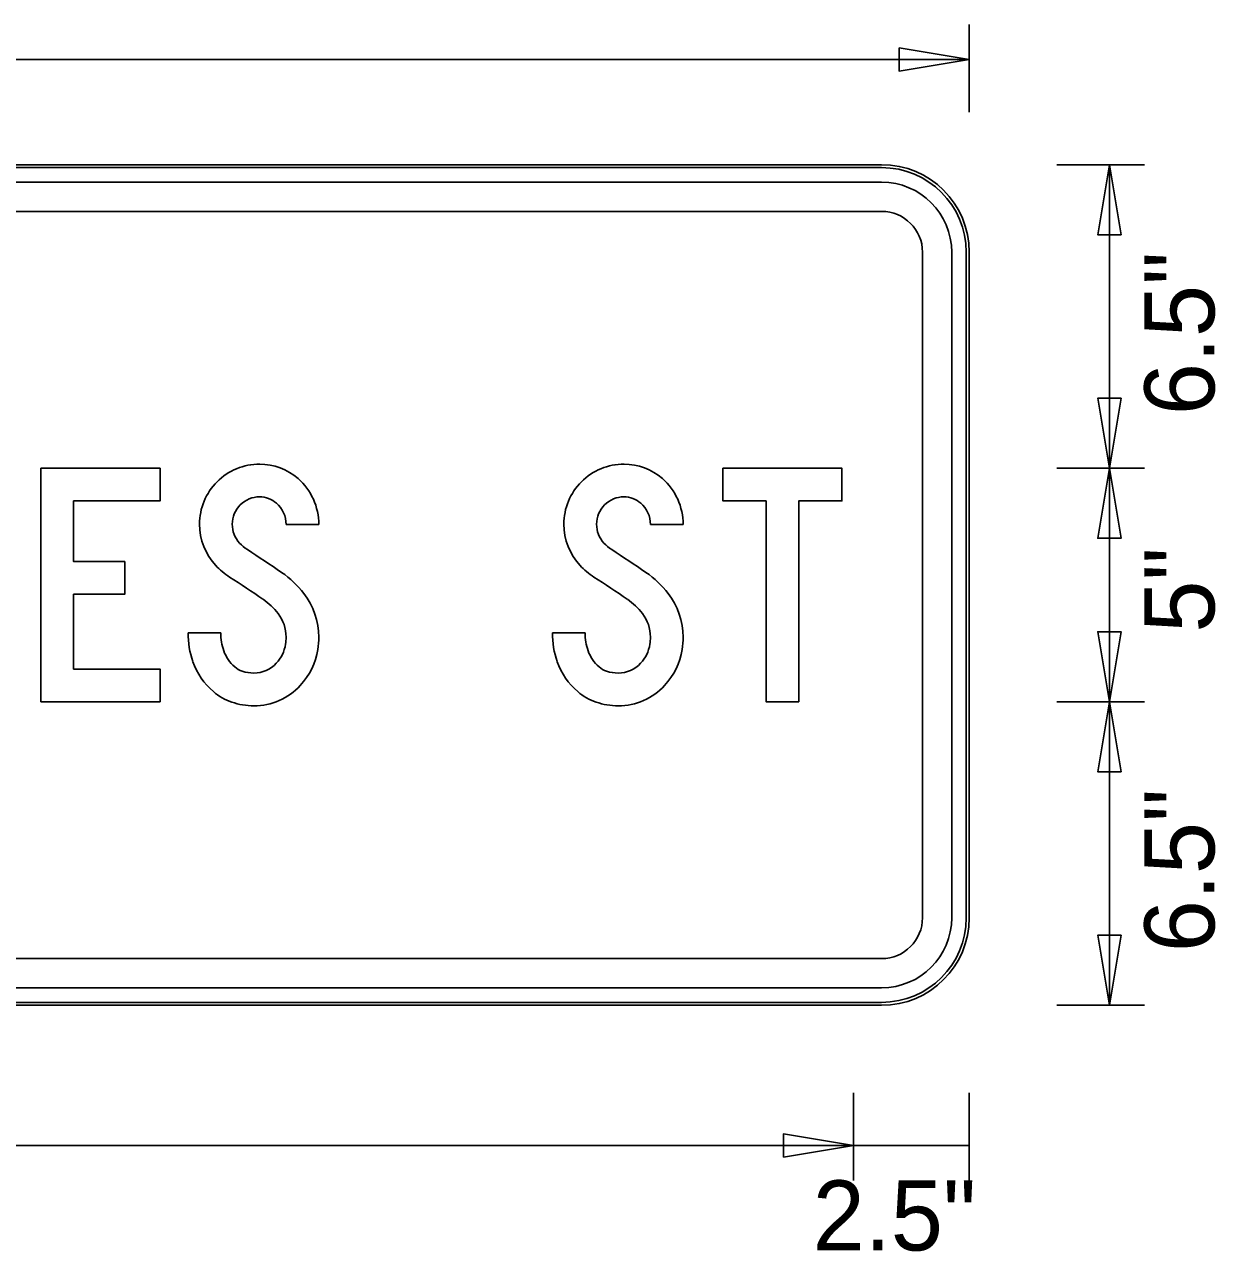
# Model space of a CAD drawing. Extents: x 1788.1 to 1851.2, y 237.2 to 283.4.
# Drawn here: x 1841.615 to 1844.165, y 250.141 to 252.768 of the extents above; entities that cross this region are included whole.
import ezdxf

# ---------------------------------------------------------------- set-up
doc = ezdxf.new("R2010")
doc.units = 0
for name, color, linetype in [('GSBWFILL', 7, 'Continuous'), ('GSCOLORFILL', 7, 'Continuous'), ('GSDIMS', 7, 'Continuous'), ('GSOUTLINE', 7, 'Continuous')]:
    doc.layers.add(name, color=color, linetype=linetype)

msp = doc.modelspace()

# ---------------------------------------------------------------- linework, layer by layer
at = {"layer": 'GSBWFILL'}
for p, q in [((1843.4504, 252.4677), (1839.0254, 252.4677)), ((1843.4504, 252.4302), (1839.0254, 252.4302)), ((1839.0254, 252.3677), (1843.4504, 252.3677)), ((1843.5379, 252.2802), (1843.5379, 250.8552)), ((1843.6004, 250.8552), (1843.6004, 252.2802)), ((1843.6379, 250.8552), (1843.6379, 252.2802)), ((1843.4504, 250.7677), (1839.026, 250.7677)), ((1839.026, 250.7052), (1843.4504, 250.7052)), ((1839.0254, 250.6677), (1843.4504, 250.6677))]:
    msp.add_line(p, q, dxfattribs=at)
for points in [[(1841.7204, 251.3877), (1841.7204, 251.5477), (1841.8299, 251.5477), (1841.8299, 251.6177), (1841.7204, 251.6177), (1841.7204, 251.7477), (1841.9054, 251.7477), (1841.9054, 251.8177), (1841.6504, 251.8177), (1841.6504, 251.3177), (1841.9054, 251.3177), (1841.9054, 251.3877)], [(1843.2029, 251.7477), (1843.1104, 251.7477), (1843.1104, 251.8177), (1843.3654, 251.8177), (1843.3654, 251.7477), (1843.2729, 251.7477), (1843.2729, 251.3177), (1843.2029, 251.3177)]]:
    msp.add_lwpolyline(points, close=True, dxfattribs=at)
for points in [[(1842.1754, 251.6973), (1842.2454, 251.6973)], [(1842.9554, 251.6973), (1843.0254, 251.6973)], [(1842.0354, 251.4649), (1841.9654, 251.4649)], [(1842.8154, 251.4649), (1842.7454, 251.4649)]]:
    msp.add_lwpolyline(points, dxfattribs=at)
for centre, radius, start, end in [((1843.4504, 252.2802), 0.1875, 0, 90), ((1843.4504, 252.2802), 0.15, 0, 90), ((1843.4504, 252.2802), 0.0875, 0, 90), ((1843.4504, 250.8552), 0.15, 270, 0), ((1843.4504, 250.8552), 0.0875, 270, 0), ((1843.4504, 250.8552), 0.1875, 270, 0)]:
    msp.add_arc(centre, radius, start, end, dxfattribs=at)
for centre, major_axis, start_param, end_param in [((1842.1188, 251.6977), (0, 0.1288), 6.283184, 7.853982), ((1842.1188, 251.7021), (0, 0.1244), 5.561989, 6.283185), ((1842.8988, 251.6977), (0, 0.1288), 6.283184, 7.853982), ((1842.8988, 251.7021), (0, 0.1244), 5.561989, 6.283185), ((1842.1147, 251.6973), (0, 0.1307), 4.712389, 5.561989), ((1842.8947, 251.6973), (0, 0.1307), 4.712389, 5.561989), ((1842.1188, 251.6977), (0, 0.0588), 6.283183, 7.853981), ((1842.1188, 251.7021), (0, 0.0544), 5.561989, 6.283185), ((1842.1147, 251.6973), (0, 0.0607), 4.712389, 5.561989), ((1842.8988, 251.6977), (0, 0.0588), 6.283183, 7.853981), ((1842.8988, 251.7021), (0, 0.0544), 5.561989, 6.283185), ((1842.8947, 251.6973), (0, 0.0607), 4.712389, 5.561989), ((1842.1191, 251.6977), (0, 0.1291), 1.570796, 2.321595), ((1842.1191, 251.6977), (0, 0.0591), 1.570796, 2.321595), ((1842.8991, 251.6977), (0, 0.1291), 1.570796, 2.321595), ((1842.8991, 251.6977), (0, 0.0591), 1.570796, 2.321595), ((1842.1403, 251.7175), (0, 0.0881), 2.321595, 2.56746), ((1842.9203, 251.7175), (0, 0.0881), 2.321595, 2.56746), ((1840.4942, 249.1726), (0, 2.9428), 5.679143, 5.709053), ((1841.2742, 249.1726), (0, 2.9428), 5.679143, 5.709053), ((1842.1403, 251.7175), (0, 0.1581), 2.321595, 2.56746), ((1842.9203, 251.7175), (0, 0.1581), 2.321595, 2.56746), ((1840.4942, 249.1726), (0, 2.8728), 5.679143, 5.709053), ((1842.0434, 251.4174), (0, 0.2153), 5.373599, 5.679143), ((1841.2742, 249.1726), (0, 2.8728), 5.679143, 5.709053), ((1842.8234, 251.4174), (0, 0.2153), 5.373599, 5.679143), ((1842.0931, 251.4561), (0, 0.1523), 4.712389, 5.373599), ((1842.8731, 251.4561), (0, 0.1523), 4.712389, 5.373599), ((1842.0434, 251.4174), (0, 0.1453), 5.373599, 5.679143), ((1842.8234, 251.4174), (0, 0.1453), 5.373599, 5.679143), ((1842.0931, 251.4561), (0, 0.0823), 4.712389, 5.373599), ((1842.8731, 251.4561), (0, 0.0823), 4.712389, 5.373599), ((1842.1498, 251.4649), (0, 0.1844), 1.570808, 1.909921), ((1842.1498, 251.4649), (0, 0.1144), 1.570816, 1.909918), ((1842.0789, 251.4561), (0, 0.0965), 4.552917, 4.712389), ((1842.0789, 251.4561), (0, 0.1665), 4.552917, 4.712389), ((1842.9298, 251.4649), (0, 0.1844), 1.570808, 1.909921), ((1842.9298, 251.4649), (0, 0.1144), 1.570816, 1.909918), ((1842.8589, 251.4561), (0, 0.0965), 4.552917, 4.712389), ((1842.8589, 251.4561), (0, 0.1665), 4.552917, 4.712389), ((1842.1182, 251.4537), (0, 0.0809), 1.909925, 2.431476), ((1842.0967, 251.4532), (0, 0.0785), 3.967076, 4.552917), ((1842.0967, 251.4532), (0, 0.1485), 3.967076, 4.552917), ((1842.8982, 251.4537), (0, 0.0809), 1.909925, 2.431476), ((1842.8767, 251.4532), (0, 0.0785), 3.967076, 4.552917), ((1842.8767, 251.4532), (0, 0.1485), 3.967076, 4.552917), ((1842.1182, 251.4537), (0, 0.1509), 1.909925, 2.431476), ((1842.0977, 251.4299), (0, 0.0495), 2.431476, 2.811358), ((1842.1064, 251.4443), (0, 0.0653), 3.141593, 3.967076), ((1842.8982, 251.4537), (0, 0.1509), 1.909925, 2.431476), ((1842.8777, 251.4299), (0, 0.0495), 2.431476, 2.811358), ((1842.8864, 251.4443), (0, 0.0653), 3.141593, 3.967076), ((1842.1064, 251.4553), (0, 0.0763), 2.811358, 3.141593), ((1842.8864, 251.4553), (0, 0.0763), 2.811358, 3.141593), ((1842.0977, 251.4299), (0, 0.1195), 2.431476, 2.811358), ((1842.1064, 251.4443), (0, 0.1353), 3.141593, 3.967076), ((1842.8777, 251.4299), (0, 0.1195), 2.431476, 2.811358), ((1842.8864, 251.4443), (0, 0.1353), 3.141593, 3.967076), ((1842.1064, 251.4553), (0, 0.1463), 2.811358, 3.141593), ((1842.8864, 251.4553), (0, 0.1463), 2.811358, 3.141593)]:
    msp.add_ellipse(centre, major_axis=major_axis, ratio=0.999991, start_param=start_param, end_param=end_param, dxfattribs=at)
at = {"layer": 'GSCOLORFILL'}
for p, q in [((1843.4504, 252.4677), (1839.0254, 252.4677)), ((1843.4504, 252.4677), (1839.0254, 252.4677)), ((1839.0254, 252.4615), (1843.4504, 252.4615)), ((1843.4504, 252.4302), (1839.0254, 252.4302)), ((1839.0254, 252.3677), (1843.4504, 252.3677)), ((1843.5379, 252.2802), (1843.5379, 250.8552)), ((1843.6004, 250.8552), (1843.6004, 252.2802)), ((1843.6316, 252.2802), (1843.6316, 250.8552)), ((1843.6379, 250.8552), (1843.6379, 252.2802)), ((1843.6379, 250.8552), (1843.6379, 252.2802)), ((1843.4504, 250.7677), (1839.026, 250.7677)), ((1839.026, 250.7052), (1843.4504, 250.7052)), ((1839.0254, 250.6677), (1843.4504, 250.6677)), ((1843.4504, 250.674), (1839.0255, 250.674)), ((1839.0255, 250.6677), (1843.4504, 250.6677))]:
    msp.add_line(p, q, dxfattribs=at)
for points in [[(1841.7204, 251.3877), (1841.7204, 251.5477), (1841.8299, 251.5477), (1841.8299, 251.6177), (1841.7204, 251.6177), (1841.7204, 251.7477), (1841.9054, 251.7477), (1841.9054, 251.8177), (1841.6504, 251.8177), (1841.6504, 251.3177), (1841.9054, 251.3177), (1841.9054, 251.3877)], [(1843.2029, 251.7477), (1843.1104, 251.7477), (1843.1104, 251.8177), (1843.3654, 251.8177), (1843.3654, 251.7477), (1843.2729, 251.7477), (1843.2729, 251.3177), (1843.2029, 251.3177)]]:
    msp.add_lwpolyline(points, close=True, dxfattribs=at)
for points in [[(1842.1754, 251.6973), (1842.2454, 251.6973)], [(1842.9554, 251.6973), (1843.0254, 251.6973)], [(1842.0354, 251.4649), (1841.9654, 251.4649)], [(1842.8154, 251.4649), (1842.7454, 251.4649)]]:
    msp.add_lwpolyline(points, dxfattribs=at)
for centre, radius, start, end in [((1843.4504, 252.2802), 0.1875, 0, 90), ((1843.4504, 252.2802), 0.1875, 0, 90), ((1843.4504, 252.2802), 0.1812, 0, 90), ((1843.4504, 252.2802), 0.15, 0, 90), ((1843.4504, 252.2802), 0.0875, 0, 90), ((1843.4504, 250.8552), 0.1875, 270, 0), ((1843.4504, 250.8552), 0.15, 270, 0), ((1843.4504, 250.8552), 0.0875, 270, 0), ((1843.4504, 250.8552), 0.1875, 270, 0), ((1843.4504, 250.8552), 0.1812, 270, 0)]:
    msp.add_arc(centre, radius, start, end, dxfattribs=at)
for centre, major_axis, start_param, end_param in [((1842.1188, 251.6977), (0, 0.1288), 6.283184, 7.853982), ((1842.1188, 251.7021), (0, 0.1244), 5.561989, 6.283185), ((1842.8988, 251.6977), (0, 0.1288), 6.283184, 7.853982), ((1842.8988, 251.7021), (0, 0.1244), 5.561989, 6.283185), ((1842.1147, 251.6973), (0, 0.1307), 4.712389, 5.561989), ((1842.8947, 251.6973), (0, 0.1307), 4.712389, 5.561989), ((1842.1188, 251.6977), (0, 0.0588), 6.283183, 7.853981), ((1842.1188, 251.7021), (0, 0.0544), 5.561989, 6.283185), ((1842.1147, 251.6973), (0, 0.0607), 4.712389, 5.561989), ((1842.8988, 251.6977), (0, 0.0588), 6.283183, 7.853981), ((1842.8988, 251.7021), (0, 0.0544), 5.561989, 6.283185), ((1842.8947, 251.6973), (0, 0.0607), 4.712389, 5.561989), ((1842.1191, 251.6977), (0, 0.1291), 1.570796, 2.321595), ((1842.1191, 251.6977), (0, 0.0591), 1.570796, 2.321595), ((1842.8991, 251.6977), (0, 0.1291), 1.570796, 2.321595), ((1842.8991, 251.6977), (0, 0.0591), 1.570796, 2.321595), ((1842.1403, 251.7175), (0, 0.0881), 2.321595, 2.56746), ((1842.9203, 251.7175), (0, 0.0881), 2.321595, 2.56746), ((1840.4942, 249.1726), (0, 2.9428), 5.679143, 5.709053), ((1841.2742, 249.1726), (0, 2.9428), 5.679143, 5.709053), ((1842.1403, 251.7175), (0, 0.1581), 2.321595, 2.56746), ((1842.9203, 251.7175), (0, 0.1581), 2.321595, 2.56746), ((1840.4942, 249.1726), (0, 2.8728), 5.679143, 5.709053), ((1842.0434, 251.4174), (0, 0.2153), 5.373599, 5.679143), ((1841.2742, 249.1726), (0, 2.8728), 5.679143, 5.709053), ((1842.8234, 251.4174), (0, 0.2153), 5.373599, 5.679143), ((1842.0931, 251.4561), (0, 0.1523), 4.712389, 5.373599), ((1842.8731, 251.4561), (0, 0.1523), 4.712389, 5.373599), ((1842.0434, 251.4174), (0, 0.1453), 5.373599, 5.679143), ((1842.8234, 251.4174), (0, 0.1453), 5.373599, 5.679143), ((1842.0931, 251.4561), (0, 0.0823), 4.712389, 5.373599), ((1842.8731, 251.4561), (0, 0.0823), 4.712389, 5.373599), ((1842.1498, 251.4649), (0, 0.1844), 1.570808, 1.909921), ((1842.1498, 251.4649), (0, 0.1144), 1.570816, 1.909918), ((1842.0789, 251.4561), (0, 0.0965), 4.552917, 4.712389), ((1842.0789, 251.4561), (0, 0.1665), 4.552917, 4.712389), ((1842.9298, 251.4649), (0, 0.1844), 1.570808, 1.909921), ((1842.9298, 251.4649), (0, 0.1144), 1.570816, 1.909918), ((1842.8589, 251.4561), (0, 0.0965), 4.552917, 4.712389), ((1842.8589, 251.4561), (0, 0.1665), 4.552917, 4.712389), ((1842.1182, 251.4537), (0, 0.0809), 1.909925, 2.431476), ((1842.0967, 251.4532), (0, 0.0785), 3.967076, 4.552917), ((1842.0967, 251.4532), (0, 0.1485), 3.967076, 4.552917), ((1842.8982, 251.4537), (0, 0.0809), 1.909925, 2.431476), ((1842.8767, 251.4532), (0, 0.0785), 3.967076, 4.552917), ((1842.8767, 251.4532), (0, 0.1485), 3.967076, 4.552917), ((1842.1182, 251.4537), (0, 0.1509), 1.909925, 2.431476), ((1842.0977, 251.4299), (0, 0.0495), 2.431476, 2.811358), ((1842.1064, 251.4443), (0, 0.0653), 3.141593, 3.967076), ((1842.8982, 251.4537), (0, 0.1509), 1.909925, 2.431476), ((1842.8777, 251.4299), (0, 0.0495), 2.431476, 2.811358), ((1842.8864, 251.4443), (0, 0.0653), 3.141593, 3.967076), ((1842.1064, 251.4553), (0, 0.0763), 2.811358, 3.141593), ((1842.8864, 251.4553), (0, 0.0763), 2.811358, 3.141593), ((1842.0977, 251.4299), (0, 0.1195), 2.431476, 2.811358), ((1842.1064, 251.4443), (0, 0.1353), 3.141593, 3.967076), ((1842.8777, 251.4299), (0, 0.1195), 2.431476, 2.811358), ((1842.8864, 251.4443), (0, 0.1353), 3.141593, 3.967076), ((1842.1064, 251.4553), (0, 0.1463), 2.811358, 3.141593), ((1842.8864, 251.4553), (0, 0.1463), 2.811358, 3.141593)]:
    msp.add_ellipse(centre, major_axis=major_axis, ratio=0.999991, start_param=start_param, end_param=end_param, dxfattribs=at)
at = {"layer": 'GSDIMS'}
for p, q in [((1843.6379, 252.5802), (1843.6379, 252.7677)), ((1838.8379, 252.6927), (1843.6379, 252.6927)), ((1843.6379, 252.5802), (1843.6379, 252.5802)), ((1843.8254, 252.4677), (1844.0129, 252.4677)), ((1843.8254, 252.4677), (1843.8254, 252.4677)), ((1843.9379, 251.8177), (1843.9379, 252.4677)), ((1843.8254, 251.8177), (1844.0129, 251.8177)), ((1843.8254, 251.8177), (1844.0129, 251.8177)), ((1843.9379, 251.8177), (1843.9379, 251.3177)), ((1843.8254, 251.3177), (1844.0129, 251.3177)), ((1843.8254, 251.3177), (1844.0129, 251.3177)), ((1843.9379, 250.6677), (1843.9379, 251.3177)), ((1843.8254, 250.6677), (1844.0129, 250.6677)), ((1843.8254, 250.6677), (1843.8254, 250.6677)), ((1843.3904, 250.4802), (1843.3904, 250.2927)), ((1843.3904, 250.4802), (1843.3904, 250.2927)), ((1843.6379, 250.4802), (1843.6379, 250.2927)), ((1843.6379, 250.4802), (1843.6379, 250.2927)), ((1839.0854, 250.3677), (1843.3904, 250.3677)), ((1843.3904, 250.3677), (1843.6379, 250.3677))]:
    msp.add_line(p, q, dxfattribs=at)
for points in [[(1843.6379, 252.6927), (1843.4879, 252.6677), (1843.4879, 252.7177)], [(1843.9379, 252.4677), (1843.9129, 252.3177), (1843.9629, 252.3177)], [(1843.9379, 251.8177), (1843.9129, 251.9677), (1843.9629, 251.9677)], [(1843.9379, 251.8177), (1843.9129, 251.6677), (1843.9629, 251.6677)], [(1843.9379, 251.3177), (1843.9129, 251.4677), (1843.9629, 251.4677)], [(1843.9379, 251.3177), (1843.9129, 251.1677), (1843.9629, 251.1677)], [(1843.9379, 250.6677), (1843.9129, 250.8177), (1843.9629, 250.8177)], [(1843.3904, 250.3677), (1843.2404, 250.3927), (1843.2404, 250.3427)]]:
    msp.add_lwpolyline(points, close=True, dxfattribs=at)
at = {"layer": 'GSOUTLINE'}
for p, q in [((1843.4504, 252.4677), (1839.0254, 252.4677)), ((1843.4504, 252.4302), (1839.0254, 252.4302)), ((1843.4504, 252.3677), (1839.0254, 252.3677)), ((1843.5379, 250.8552), (1843.5379, 252.2802)), ((1843.6004, 250.8552), (1843.6004, 252.2802)), ((1843.6379, 250.8552), (1843.6379, 252.2802)), ((1839.0254, 250.7677), (1843.4504, 250.7677)), ((1839.0254, 250.7052), (1843.4504, 250.7052)), ((1839.0254, 250.6677), (1843.4504, 250.6677))]:
    msp.add_line(p, q, dxfattribs=at)
for points in [[(1841.7204, 251.3877), (1841.7204, 251.5477), (1841.8299, 251.5477), (1841.8299, 251.6177), (1841.7204, 251.6177), (1841.7204, 251.7477), (1841.9054, 251.7477), (1841.9054, 251.8177), (1841.6504, 251.8177), (1841.6504, 251.3177), (1841.9054, 251.3177), (1841.9054, 251.3877)], [(1843.2029, 251.7477), (1843.1104, 251.7477), (1843.1104, 251.8177), (1843.3654, 251.8177), (1843.3654, 251.7477), (1843.2729, 251.7477), (1843.2729, 251.3177), (1843.2029, 251.3177)]]:
    msp.add_lwpolyline(points, close=True, dxfattribs=at)
for points in [[(1842.1754, 251.6973), (1842.2454, 251.6973)], [(1842.9554, 251.6973), (1843.0254, 251.6973)], [(1842.0354, 251.4649), (1841.9654, 251.4649)], [(1842.8154, 251.4649), (1842.7454, 251.4649)]]:
    msp.add_lwpolyline(points, dxfattribs=at)
for centre, radius, start, end in [((1843.4504, 252.2802), 0.1875, 0, 90), ((1843.4504, 252.2802), 0.15, 0, 90), ((1843.4504, 252.2802), 0.0875, 0, 90), ((1843.4504, 250.8552), 0.15, 270, 0), ((1843.4504, 250.8552), 0.0875, 270, 0), ((1843.4504, 250.8552), 0.1875, 270, 0)]:
    msp.add_arc(centre, radius, start, end, dxfattribs=at)
for centre, major_axis, start_param, end_param in [((1842.1188, 251.6977), (0, 0.1288), 6.283184, 7.853982), ((1842.1188, 251.7021), (0, 0.1244), 5.561989, 6.283185), ((1842.8988, 251.6977), (0, 0.1288), 6.283184, 7.853982), ((1842.8988, 251.7021), (0, 0.1244), 5.561989, 6.283185), ((1842.1147, 251.6973), (0, 0.1307), 4.712389, 5.561989), ((1842.8947, 251.6973), (0, 0.1307), 4.712389, 5.561989), ((1842.1188, 251.6977), (0, 0.0588), 6.283183, 7.853981), ((1842.1188, 251.7021), (0, 0.0544), 5.561989, 6.283185), ((1842.1147, 251.6973), (0, 0.0607), 4.712389, 5.561989), ((1842.8988, 251.6977), (0, 0.0588), 6.283183, 7.853981), ((1842.8988, 251.7021), (0, 0.0544), 5.561989, 6.283185), ((1842.8947, 251.6973), (0, 0.0607), 4.712389, 5.561989), ((1842.1191, 251.6977), (0, 0.1291), 1.570796, 2.321595), ((1842.1191, 251.6977), (0, 0.0591), 1.570796, 2.321595), ((1842.8991, 251.6977), (0, 0.1291), 1.570796, 2.321595), ((1842.8991, 251.6977), (0, 0.0591), 1.570796, 2.321595), ((1842.1403, 251.7175), (0, 0.0881), 2.321595, 2.56746), ((1842.9203, 251.7175), (0, 0.0881), 2.321595, 2.56746), ((1840.4942, 249.1726), (0, 2.9428), 5.679143, 5.709053), ((1841.2742, 249.1726), (0, 2.9428), 5.679143, 5.709053), ((1842.1403, 251.7175), (0, 0.1581), 2.321595, 2.56746), ((1842.9203, 251.7175), (0, 0.1581), 2.321595, 2.56746), ((1840.4942, 249.1726), (0, 2.8728), 5.679143, 5.709053), ((1842.0434, 251.4174), (0, 0.2153), 5.373599, 5.679143), ((1841.2742, 249.1726), (0, 2.8728), 5.679143, 5.709053), ((1842.8234, 251.4174), (0, 0.2153), 5.373599, 5.679143), ((1842.0931, 251.4561), (0, 0.1523), 4.712389, 5.373599), ((1842.8731, 251.4561), (0, 0.1523), 4.712389, 5.373599), ((1842.0434, 251.4174), (0, 0.1453), 5.373599, 5.679143), ((1842.8234, 251.4174), (0, 0.1453), 5.373599, 5.679143), ((1842.0931, 251.4561), (0, 0.0823), 4.712389, 5.373599), ((1842.8731, 251.4561), (0, 0.0823), 4.712389, 5.373599), ((1842.1498, 251.4649), (0, 0.1844), 1.570808, 1.909921), ((1842.1498, 251.4649), (0, 0.1144), 1.570816, 1.909918), ((1842.0789, 251.4561), (0, 0.0965), 4.552917, 4.712389), ((1842.0789, 251.4561), (0, 0.1665), 4.552917, 4.712389), ((1842.9298, 251.4649), (0, 0.1844), 1.570808, 1.909921), ((1842.9298, 251.4649), (0, 0.1144), 1.570816, 1.909918), ((1842.8589, 251.4561), (0, 0.0965), 4.552917, 4.712389), ((1842.8589, 251.4561), (0, 0.1665), 4.552917, 4.712389), ((1842.1182, 251.4537), (0, 0.0809), 1.909925, 2.431476), ((1842.0967, 251.4532), (0, 0.0785), 3.967076, 4.552917), ((1842.0967, 251.4532), (0, 0.1485), 3.967076, 4.552917), ((1842.8982, 251.4537), (0, 0.0809), 1.909925, 2.431476), ((1842.8767, 251.4532), (0, 0.0785), 3.967076, 4.552917), ((1842.8767, 251.4532), (0, 0.1485), 3.967076, 4.552917), ((1842.1182, 251.4537), (0, 0.1509), 1.909925, 2.431476), ((1842.0977, 251.4299), (0, 0.0495), 2.431476, 2.811358), ((1842.1064, 251.4443), (0, 0.0653), 3.141593, 3.967076), ((1842.8982, 251.4537), (0, 0.1509), 1.909925, 2.431476), ((1842.8777, 251.4299), (0, 0.0495), 2.431476, 2.811358), ((1842.8864, 251.4443), (0, 0.0653), 3.141593, 3.967076), ((1842.1064, 251.4553), (0, 0.0763), 2.811358, 3.141593), ((1842.8864, 251.4553), (0, 0.0763), 2.811358, 3.141593), ((1842.0977, 251.4299), (0, 0.1195), 2.431476, 2.811358), ((1842.1064, 251.4443), (0, 0.1353), 3.141593, 3.967076), ((1842.8777, 251.4299), (0, 0.1195), 2.431476, 2.811358), ((1842.8864, 251.4443), (0, 0.1353), 3.141593, 3.967076), ((1842.1064, 251.4553), (0, 0.1463), 2.811358, 3.141593), ((1842.8864, 251.4553), (0, 0.1463), 2.811358, 3.141593)]:
    msp.add_ellipse(centre, major_axis=major_axis, ratio=0.999991, start_param=start_param, end_param=end_param, dxfattribs=at)

# ---------------------------------------------------------------- texts
at = {"layer": 'GSDIMS'}
for s, p in [('6.5"', (1844.1629, 251.9314)), ('5"', (1844.1629, 251.4657)), ('6.5"', (1844.1629, 250.7814))]:
    msp.add_text(s, height=0.15, rotation=90, dxfattribs=at).set_placement(p)
msp.add_text('2.5"', height=0.15, dxfattribs=at).set_placement((1843.3028, 250.1427))

doc.saveas('drawing.dxf')
